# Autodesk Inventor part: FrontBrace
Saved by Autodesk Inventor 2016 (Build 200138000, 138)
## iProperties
Created: 2016-03
Part Number: FrontBrace
Material: Generic
Document SubType Name: Modeling
Designer: bongo_000
Density: 1 g/cm^3
Appearance: Default
Author: bongo_000
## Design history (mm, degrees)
feature "Base1"
body "Solid1"
